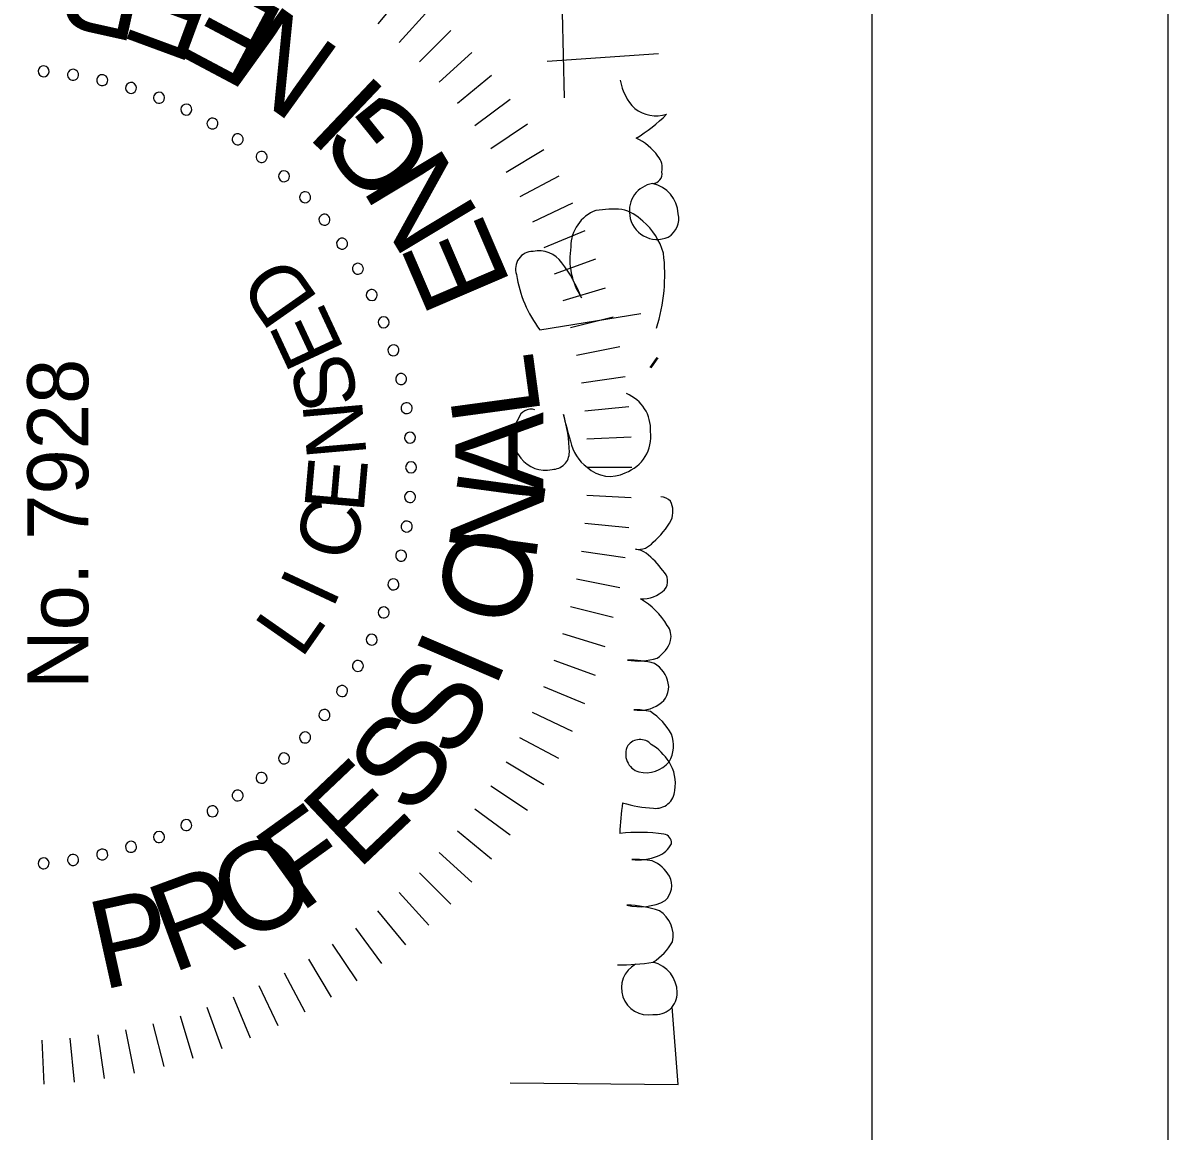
# Model space of a CAD drawing. Extents: x 916060 to 916918, y 329833 to 330383.
# Drawn here: x 916873.12 to 916910.03, y 330205.41 to 330241.13 of the extents above; entities that cross this region are included whole.
import ezdxf

# ---------------------------------------------------------------- set-up
doc = ezdxf.new("R2010")
doc.units = 0
for name, color, linetype in [('Border', 7, 'Continuous'), ('Default', 7, 'Continuous'), ('PLOT BOUNDARY', 7, 'Continuous')]:
    doc.layers.add(name, color=color, linetype=linetype)

# ---------------------------------------------------------------- blocks, each defined once
blk = doc.blocks.new('STAMP')
at = {"layer": 'Default'}
for p, q in [((-0.007955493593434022, 0.0011091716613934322), (-0.007387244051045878, 0.0011370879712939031)), ((-0.007926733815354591, 0.0007192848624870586), (-0.007360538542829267, 0.0007750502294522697)), ((-0.007878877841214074, 0.0003312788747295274), (-0.0073161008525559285, 0.00041475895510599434)), ((-0.007812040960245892, -5.391156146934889e-05), (-0.007254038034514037, 5.708212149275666e-05)), ((-0.0077263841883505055, -0.0004353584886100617), (-0.0071744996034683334, -0.00029711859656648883)), ((-0.007622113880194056, -0.0008121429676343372), (-0.007077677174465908, -0.0006469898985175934)), ((-0.00749948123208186, -0.0011833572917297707), (-0.0069638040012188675, -0.00099168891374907)), ((-0.007358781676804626, -0.0015481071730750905), (-0.006833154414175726, -0.001330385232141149)), ((-0.007200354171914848, -0.0019055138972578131), (-0.006686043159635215, -0.0016622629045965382)), ((-0.007024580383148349, -0.0022547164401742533), (-0.0065228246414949, -0.001986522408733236)), ((-0.006831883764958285, -0.002594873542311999), (-0.006343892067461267, -0.0023023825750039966)), ((-0.006622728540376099, -0.002925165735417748), (-0.0061496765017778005, -0.0026090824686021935)), ((-0.00639761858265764, -0.0032447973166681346), (-0.005940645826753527, -0.0029058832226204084)), ((-0.006157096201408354, -0.003552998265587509), (-0.005717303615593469, -0.0031920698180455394)), ((0.006157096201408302, -0.0035529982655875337), (0.005717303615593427, -0.0031920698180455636)), ((-0.005901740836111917, -0.003849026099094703), (-0.005480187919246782, -0.0034669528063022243)), ((0.005901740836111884, -0.0038490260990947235), (0.005480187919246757, -0.0034669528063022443)), ((-0.0056321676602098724, -0.0041321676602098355), (-0.00522986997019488, -0.003729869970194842)), ((0.00563216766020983, -0.0041321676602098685), (0.0052298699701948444, -0.0037298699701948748)), ((-0.005349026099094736, -0.004401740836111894), (-0.004966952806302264, -0.003980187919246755)), ((0.005349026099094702, -0.004401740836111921), (0.004966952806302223, -0.003980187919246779)), ((-0.0050529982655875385, -0.004657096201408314), (-0.004692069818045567, -0.004217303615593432)), ((0.005052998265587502, -0.004657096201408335), (0.004692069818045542, -0.004217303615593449)), ((-0.004744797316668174, -0.0048976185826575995), (-0.004405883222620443, -0.004440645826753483)), ((0.004744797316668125, -0.0048976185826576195), (0.004405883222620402, -0.0044406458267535)), ((-0.0044251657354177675, -0.005122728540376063), (-0.004109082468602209, -0.004649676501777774)), ((0.004425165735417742, -0.00512272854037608), (0.004109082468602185, -0.004649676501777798)), ((-0.004094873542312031, -0.005331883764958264), (-0.0038023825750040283, -0.004843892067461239)), ((0.0040948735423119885, -0.005331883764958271), (0.003802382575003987, -0.004843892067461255)), ((-0.0037547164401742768, -0.005524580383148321), (-0.0034865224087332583, -0.005022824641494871)), ((0.0037547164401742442, -0.005524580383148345), (0.003486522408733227, -0.005022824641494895)), ((-0.003405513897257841, -0.005700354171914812), (-0.0031622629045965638, -0.0051860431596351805)), ((0.0034055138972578, -0.005700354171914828), (0.003162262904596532, -0.005186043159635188)), ((-0.003048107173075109, -0.005858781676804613), (-0.0028303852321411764, -0.005333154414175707)), ((0.003048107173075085, -0.005858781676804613), (0.002830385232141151, -0.005333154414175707)), ((0.00523613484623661, -0.005376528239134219), (0.005338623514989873, -0.0068089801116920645)), ((-0.0026833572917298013, -0.005999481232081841), (-0.002491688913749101, -0.005463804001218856)), ((-0.0023121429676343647, -0.006122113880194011), (-0.0021469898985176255, -0.005577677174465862)), ((0.0023121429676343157, -0.006122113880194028), (0.0021469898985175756, -0.005577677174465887)), ((0.002683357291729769, -0.005999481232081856), (0.0024916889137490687, -0.005463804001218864)), ((0.004764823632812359, -0.005597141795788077), (0.005863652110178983, -0.005572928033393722)), ((-0.0019353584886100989, -0.006226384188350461), (-0.0017971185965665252, -0.005674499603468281)), ((-0.0015539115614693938, -0.006312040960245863), (-0.0014429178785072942, -0.005754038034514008)), ((0.0015539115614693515, -0.006312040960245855), (0.0014429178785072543, -0.005754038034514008)), ((0.0019353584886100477, -0.006226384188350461), (0.0017971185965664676, -0.005674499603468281)), ((-0.001168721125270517, -0.006378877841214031), (-0.0010852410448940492, -0.005816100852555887)), ((-0.0007807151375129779, -0.006426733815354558), (-0.0007249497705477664, -0.0058605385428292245)), ((-0.00039082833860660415, -0.006455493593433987), (-0.00036291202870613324, -0.005887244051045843)), ((-2.0539125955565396e-17, -0.006465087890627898), (-2.0539125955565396e-17, -0.005896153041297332)), ((0.0003908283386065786, -0.0064554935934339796), (0.0003629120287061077, -0.005887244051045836)), ((0.0007807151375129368, -0.006426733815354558), (0.0007249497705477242, -0.005860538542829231)), ((0.0011687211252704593, -0.006378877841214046), (0.0010852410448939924, -0.005816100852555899)), ((0.001282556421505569, -0.006716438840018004), (0.001411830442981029, -0.006805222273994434)), ((0.0012888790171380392, -0.0067038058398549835), (0.0014181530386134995, -0.006792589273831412))]:
    blk.add_line(p, q, dxfattribs=at)
for points in [[(-0.007938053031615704, -0.004895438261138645), (-0.007956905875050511, -0.007061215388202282), (-0.0069577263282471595, -0.006985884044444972)], [(0.0017747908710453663, -0.005281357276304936), (0.001982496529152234, -0.006583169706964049)]]:
    blk.add_lwpolyline(points, dxfattribs=at)
for centre, radius, start, end in [((-0.005106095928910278, 0.0011173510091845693), 7.111685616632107e-05, 94.28571428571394, 274.28571428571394), ((-0.005106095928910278, 0.0011173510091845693), 7.11168561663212e-05, 274.28571428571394, 94.28571428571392), ((0.005106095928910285, 0.0011173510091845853), 7.11168561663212e-05, 85.71428571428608, 265.71428571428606), ((0.005106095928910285, 0.0011173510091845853), 7.11168561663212e-05, 265.71428571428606, 85.71428571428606), ((-0.005063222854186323, 0.0007368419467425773), 7.111685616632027e-05, 98.5714285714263, 278.5714285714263), ((-0.005063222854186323, 0.0007368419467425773), 7.111685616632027e-05, 278.5714285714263, 98.5714285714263), ((0.005063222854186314, 0.0007368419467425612), 7.111685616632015e-05, 81.42857142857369, 261.4285714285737), ((0.005063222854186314, 0.0007368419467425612), 7.111685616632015e-05, 261.4285714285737, 81.42857142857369), ((-0.0049920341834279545, 0.00036060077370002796), 7.11168561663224e-05, 102.8571428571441, 282.8571428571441), ((-0.0049920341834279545, 0.00036060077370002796), 7.11168561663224e-05, 282.8571428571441, 102.85714285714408), ((0.004992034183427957, 0.00036060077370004), 7.111685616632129e-05, 77.14285714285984, 257.14285714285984), ((0.004992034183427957, 0.00036060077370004), 7.111685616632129e-05, 257.14285714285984, 77.14285714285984), ((-0.004892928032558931, -9.26841668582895e-06), 7.111685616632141e-05, 107.14285714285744, 287.14285714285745), ((-0.004892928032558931, -9.26841668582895e-06), 7.111685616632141e-05, 287.14285714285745, 107.14285714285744), ((0.004892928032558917, -9.268416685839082e-06), 7.111685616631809e-05, 72.85714285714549, 252.8571428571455), ((0.004892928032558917, -9.268416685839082e-06), 7.111685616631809e-05, 252.85714285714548, 72.85714285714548), ((-0.004766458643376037, -0.00037069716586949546), 7.111685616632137e-05, 111.42857142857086, 291.4285714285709), ((-0.004766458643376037, -0.00037069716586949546), 7.111685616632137e-05, 291.4285714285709, 111.42857142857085), ((0.0047664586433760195, -0.00037069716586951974), 7.111685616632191e-05, 68.57142857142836, 248.57142857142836), ((0.0047664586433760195, -0.00037069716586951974), 7.111685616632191e-05, 248.57142857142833, 68.57142857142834), ((-0.0046133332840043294, -0.0007216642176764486), 7.1116856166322e-05, 115.71428571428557, 295.71428571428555), ((-0.0046133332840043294, -0.0007216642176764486), 7.1116856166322e-05, 295.71428571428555, 115.71428571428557), ((0.0046133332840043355, -0.0007216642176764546), 7.111685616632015e-05, 64.28571428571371, 244.2857142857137), ((0.0046133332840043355, -0.0007216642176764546), 7.111685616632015e-05, 244.2857142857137, 64.2857142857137), ((-0.004434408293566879, -0.0010602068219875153), 7.111685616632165e-05, 119.99999999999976, 299.9999999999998), ((-0.004434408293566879, -0.0010602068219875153), 7.111685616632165e-05, 299.9999999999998, 119.99999999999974), ((0.00443440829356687, -0.0010602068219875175), 7.111685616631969e-05, 59.99999999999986, 239.99999999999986), ((0.00443440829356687, -0.0010602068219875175), 7.111685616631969e-05, 239.99999999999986, 59.99999999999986), ((-0.004230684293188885, -0.0013844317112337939), 7.111685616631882e-05, 124.28571428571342, 304.2857142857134), ((-0.004230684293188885, -0.0013844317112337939), 7.111685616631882e-05, 304.2857142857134, 124.28571428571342), ((0.004230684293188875, -0.0013844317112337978), 7.111685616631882e-05, 55.714285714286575, 235.71428571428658), ((0.004230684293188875, -0.0013844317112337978), 7.111685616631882e-05, 235.71428571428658, 55.714285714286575), ((-0.004003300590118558, -0.0016925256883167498), 7.111685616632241e-05, 308.5714285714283, 128.57142857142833), ((0.004003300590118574, -0.0016925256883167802), 7.111685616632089e-05, 51.42857142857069, 231.4285714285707), ((-0.004003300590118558, -0.0016925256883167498), 7.111685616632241e-05, 128.57142857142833, 308.5714285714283), ((0.004003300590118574, -0.0016925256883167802), 7.111685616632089e-05, 231.42857142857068, 51.42857142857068), ((-0.003753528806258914, -0.0019827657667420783), 7.11168561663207e-05, 312.85714285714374, 132.85714285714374), ((0.003753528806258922, -0.0019827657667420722), 7.111685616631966e-05, 47.14285714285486, 227.14285714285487), ((-0.003753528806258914, -0.0019827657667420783), 7.11168561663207e-05, 132.85714285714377, 312.8571428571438), ((0.003753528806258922, -0.0019827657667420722), 7.111685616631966e-05, 227.14285714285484, 47.14285714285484), ((-0.0034827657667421, -0.002253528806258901), 7.111685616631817e-05, 137.14285714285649, 317.1428571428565), ((-0.0034827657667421, -0.002253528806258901), 7.111685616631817e-05, 317.1428571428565, 137.14285714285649), ((0.0034827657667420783, -0.0022535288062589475), 7.111685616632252e-05, 42.857142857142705, 222.85714285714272), ((0.0034827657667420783, -0.0022535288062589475), 7.111685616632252e-05, 222.8571428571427, 42.85714285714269), ((-0.0031925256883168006, -0.0025033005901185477), 7.111685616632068e-05, 141.42857142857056, 321.42857142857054), ((-0.0031925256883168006, -0.0025033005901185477), 7.111685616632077e-05, 321.42857142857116, 141.4285714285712), ((0.0031925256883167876, -0.002503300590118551), 7.111685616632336e-05, 38.57142857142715, 218.57142857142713), ((0.0031925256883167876, -0.002503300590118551), 7.111685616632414e-05, 218.57142857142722, 38.57142857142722), ((-0.0028844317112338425, -0.0027306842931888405), 7.111685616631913e-05, 145.7142857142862, 325.71428571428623), ((-0.0028844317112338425, -0.0027306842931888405), 7.111685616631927e-05, 325.7142857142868, 145.71428571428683), ((0.002884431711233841, -0.0027306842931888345), 7.111685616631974e-05, 34.28571428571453, 214.28571428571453), ((0.002884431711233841, -0.0027306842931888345), 7.111685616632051e-05, 214.28571428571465, 34.28571428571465), ((-0.0025602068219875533, -0.0029344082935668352), 7.111685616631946e-05, 149.99999999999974, 329.9999999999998), ((-0.0025602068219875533, -0.0029344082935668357), 7.111685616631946e-05, 329.9999999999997, 149.99999999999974), ((0.0025602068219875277, -0.0029344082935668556), 7.111685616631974e-05, 30.000000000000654, 210.00000000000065), ((0.0025602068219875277, -0.002934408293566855), 7.111685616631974e-05, 210.00000000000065, 30.000000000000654), ((-0.0022216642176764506, -0.0031133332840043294), 7.111685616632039e-05, 154.2857142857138, 334.28571428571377), ((-0.0022216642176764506, -0.0031133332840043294), 7.111685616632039e-05, 334.2857142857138, 154.2857142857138), ((0.0022216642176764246, -0.0031133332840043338), 7.111685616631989e-05, 25.714285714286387, 205.71428571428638), ((0.0022216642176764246, -0.0031133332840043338), 7.111685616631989e-05, 205.71428571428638, 25.714285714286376), ((-0.0018706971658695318, -0.003266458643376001), 7.111685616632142e-05, 158.57142857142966, 338.5714285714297), ((-0.0018706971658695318, -0.0032664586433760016), 7.111685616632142e-05, 338.57142857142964, 158.57142857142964), ((0.0018706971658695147, -0.0032664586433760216), 7.111685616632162e-05, 21.428571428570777, 201.42857142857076), ((0.0018706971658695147, -0.0032664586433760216), 7.111685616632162e-05, 201.42857142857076, 21.428571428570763), ((-0.0015092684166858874, -0.003392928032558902), 7.111685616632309e-05, 162.85714285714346, 342.85714285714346), ((-0.0015092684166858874, -0.003392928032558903), 7.111685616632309e-05, 342.85714285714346, 162.85714285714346), ((0.0015092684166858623, -0.0033929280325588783), 7.111685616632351e-05, 17.142857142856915, 197.1428571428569), ((0.0015092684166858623, -0.0033929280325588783), 7.111685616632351e-05, 197.1428571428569, 17.14285714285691), ((-0.0011393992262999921, -0.0034920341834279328), 7.111685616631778e-05, 167.14285714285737, 347.14285714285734), ((-0.0011393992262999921, -0.0034920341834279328), 7.111685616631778e-05, 347.14285714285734, 167.14285714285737), ((-0.0007631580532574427, -0.003563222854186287), 7.111685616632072e-05, 351.4285714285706, 171.4285714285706), ((-0.0003826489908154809, -0.003606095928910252), 7.111685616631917e-05, 355.7142857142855, 175.7142857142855), ((0.0003826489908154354, -0.0036060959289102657), 7.111685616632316e-05, 4.285714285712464, 184.28571428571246), ((0.0007631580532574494, -0.0035632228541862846), 7.111685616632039e-05, 8.571428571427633, 188.57142857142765), ((0.0011393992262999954, -0.0034920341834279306), 7.111685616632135e-05, 12.857142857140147, 192.85714285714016), ((0.0011393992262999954, -0.0034920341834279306), 7.111685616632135e-05, 192.85714285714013, 12.857142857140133), ((-0.0007631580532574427, -0.003563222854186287), 7.111685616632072e-05, 171.4285714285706, 351.4285714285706), ((-0.0003826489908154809, -0.003606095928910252), 7.111685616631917e-05, 175.71428571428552, 355.71428571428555), ((-1.2628786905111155e-17, -0.0036204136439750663), 7.111685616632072e-05, 0, 180), ((-1.2628786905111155e-17, -0.0036204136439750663), 7.111685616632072e-05, 180, 0), ((0.0003826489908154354, -0.0036060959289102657), 7.111685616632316e-05, 184.28571428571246, 4.285714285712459), ((0.0007631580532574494, -0.0035632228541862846), 7.111685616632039e-05, 188.57142857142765, 8.571428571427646), ((0.00039604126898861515, -0.005375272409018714), 0.00043958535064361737, 57.64755033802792, 128.97245422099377), ((0.0005805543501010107, -0.005165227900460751), 0.00016909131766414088, 342.3611945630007, 72.54487353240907), ((0.0027009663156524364, -0.006477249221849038), 0.001512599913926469, 98.17812986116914, 127.75649827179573), ((0.0025607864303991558, -0.005191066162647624), 0.0002239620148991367, 359.61429023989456, 109.56218572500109), ((0.00036114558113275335, -0.0053488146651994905), 0.0003972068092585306, 127.45926190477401, 192.9614203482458), ((0.0024288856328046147, -0.00526578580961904), 0.0003633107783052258, 304.8740098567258, 11.625468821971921), ((0.00019608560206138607, -0.005439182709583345), 0.0002220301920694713, 179.67057284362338, 269.694601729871), ((0.00015503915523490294, -0.003868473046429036), 0.001793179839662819, 271.2738092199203, 287.01217780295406), ((0.002166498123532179, -0.011827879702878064), 0.006419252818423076, 103.3923944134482, 106.55297850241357), ((0.0015502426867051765, -0.00415818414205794), 0.0017765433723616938, 290.99837671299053, 307.69878588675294), ((0.0004564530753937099, -0.0062299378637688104), 0.0005678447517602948, 102.0773813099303, 143.39383108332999), ((0.0026896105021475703, -0.006582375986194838), 0.0009159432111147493, 80.29637939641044, 123.29138431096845), ((0.0028457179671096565, -0.006179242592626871), 0.0004997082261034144, 20.58705533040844, 90.19763829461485), ((0.00031613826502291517, -0.006186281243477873), 0.0004319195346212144, 136.9297266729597, 206.7934360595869), ((0.0014539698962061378, -0.006245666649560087), 0.0018752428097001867, 357.2040173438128, 7.418903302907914), ((-0.00671307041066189, -0.006678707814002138), 0.0003465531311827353, 28.430349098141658, 189.68707560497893), ((-0.003955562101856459, -0.006312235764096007), 0.002461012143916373, 179.30402472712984, 190.0665804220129), ((-0.007015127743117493, -0.0065631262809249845), 0.0023079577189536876, 352.1195763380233, 6.249520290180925), ((-0.004786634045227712, -0.009314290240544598), 0.003003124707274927, 81.15725195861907, 88.74550427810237), ((-0.002857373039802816, -0.006810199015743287), 0.001539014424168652, 162.47862001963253, 177.5735090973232), ((0.0027994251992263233, -0.006216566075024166), 0.0005411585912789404, 313.71200852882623, 347.12598992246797), ((0.005109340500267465, -0.0069995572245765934), 0.000693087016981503, 99.83623703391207, 134.2279465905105), ((-0.007040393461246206, -0.006369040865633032), 0.0013973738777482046, 341.03759348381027, 358.5906169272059), ((-0.004987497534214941, -0.006577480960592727), 0.0006786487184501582, 165.1377733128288, 207.96825790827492), ((-0.006329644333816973, -0.006519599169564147), 0.0012732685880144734, 350.5388137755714, 2.446920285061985), ((-0.004310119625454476, -0.006538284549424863), 0.0007509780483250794, 174.41813129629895, 200.30191948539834), ((-0.0037000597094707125, -0.006623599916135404), 0.00023723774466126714, 61.91684207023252, 163.66717131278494), ((-0.0037052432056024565, -0.0065716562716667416), 0.0001960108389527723, 312.7382758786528, 53.40100716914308), ((-0.003974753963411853, -0.006503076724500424), 0.0008496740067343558, 346.26214121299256, 0.7257075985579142), ((-0.002682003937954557, -0.006568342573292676), 0.00044961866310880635, 170.2648919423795, 213.2954708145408), ((-0.00388024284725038, -0.006412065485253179), 0.0013948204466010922, 345.72048696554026, 0.12433676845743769), ((-0.0016914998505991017, -0.006545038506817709), 0.0008054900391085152, 170.27954956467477, 197.78532003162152), ((0.0003962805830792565, -0.006217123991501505), 0.0004936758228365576, 199.38474076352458, 277.55079490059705), ((0.0004891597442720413, -0.006207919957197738), 0.0004993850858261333, 266.784921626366, 337.7362429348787), ((0.0032953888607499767, -0.006791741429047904), 0.00035634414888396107, 97.37079091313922, 203.8922211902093), ((0.0033059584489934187, -0.006794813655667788), 0.0003608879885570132, 9.655140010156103, 98.97262191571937), ((-0.0035430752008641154, -0.006644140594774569), 0.0003944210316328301, 167.2189950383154, 230.16055614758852), ((-0.002536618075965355, -0.006083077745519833), 0.0009765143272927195, 300.6803608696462, 329.51258202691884), ((-0.0012666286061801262, -0.006594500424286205), 0.00042878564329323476, 177.86300386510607, 223.17874837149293), ((-0.0013865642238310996, -0.006474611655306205), 0.0003320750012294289, 327.8843366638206, 353.1980671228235), ((-0.0008025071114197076, -0.006544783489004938), 0.0002561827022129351, 173.08541670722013, 230.55848375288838), ((0.002532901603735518, -0.0060711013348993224), 0.0008355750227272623, 286.05704557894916, 320.0421489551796), ((0.003588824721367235, -0.00621969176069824), 0.0007209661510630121, 306.1913846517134, 335.23134174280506), ((0.005998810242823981, -0.005456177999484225), 0.0020534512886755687, 211.2594929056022, 225.2513717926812), ((0.004994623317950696, -0.006780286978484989), 0.0004614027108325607, 143.047197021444, 196.91634387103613), ((-0.006777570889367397, -0.006772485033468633), 0.00027937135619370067, 172.70712454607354, 271.16395527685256), ((-0.006783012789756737, -0.006633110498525), 0.0004188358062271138, 271.5209447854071, 344.87406906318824), ((-0.005754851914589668, -0.006345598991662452), 0.0007393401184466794, 212.4592088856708, 240.63114206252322), ((-0.0055308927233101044, -0.006522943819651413), 0.0005014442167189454, 301.1133493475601, 335.74975916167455), ((-0.004152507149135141, -0.006775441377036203), 0.00024439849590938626, 172.85451562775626, 266.8151593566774), ((-0.00421927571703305, -0.006314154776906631), 0.0007614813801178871, 303.79189499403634, 328.18256979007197), ((-0.0038004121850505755, -0.006299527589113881), 0.000766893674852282, 298.0105046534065, 328.09350966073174), ((-0.00285343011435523, -0.006566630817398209), 0.0003761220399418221, 280.5798823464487, 329.7517392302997), ((-0.0020051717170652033, -0.0059200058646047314), 0.0011594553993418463, 305.5205731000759, 320.90595982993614), ((-0.0001785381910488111, -0.0060637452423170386), 0.0010391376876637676, 220.79179678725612, 241.16030041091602), ((0.0024869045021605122, -0.0045618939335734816), 0.0023287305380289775, 252.701645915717, 276.8342307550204), ((0.0032445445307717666, -0.006637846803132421), 0.00042819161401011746, 273.5716384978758, 346.98387133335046), ((0.0037841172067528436, -0.006733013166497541), 0.00012238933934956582, 180.59606692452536, 282.14231124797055), ((-0.006036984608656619, -0.006622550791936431), 0.0003760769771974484, 257.6460165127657, 327.7710077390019), ((-0.005391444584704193, -0.006712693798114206), 0.0002677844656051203, 223.12676578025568, 296.5429712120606), ((-0.004715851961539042, -0.006689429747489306), 0.00031800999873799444, 200.1253724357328, 244.48124886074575), ((-0.004842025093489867, -0.006862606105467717), 0.00011432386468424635, 264.56536252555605, 351.47104640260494), ((-0.0028340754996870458, -0.006679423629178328), 0.00026169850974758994, 211.24435430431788, 280.94854976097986), ((-0.0021179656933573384, -0.00658432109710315), 0.00039838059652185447, 211.26450698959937, 253.32703764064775), ((-0.0021804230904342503, -0.006741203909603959), 0.00023065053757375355, 257.01114107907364, 308.02112433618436), ((-0.0014677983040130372, -0.006749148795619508), 0.0001780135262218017, 231.21384232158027, 319.94914487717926), ((-0.0005623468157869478, -0.006834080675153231), 0.00018159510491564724, 314.66347430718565, 358.2957841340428), ((0.003211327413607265, -0.006788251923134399), 0.0002833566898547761, 211.44349084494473, 282.2024112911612), ((0.0038601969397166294, -0.006618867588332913), 0.000239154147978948, 257.8497316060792, 310.1947013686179), ((-0.00407546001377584, -0.006500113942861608), 0.0005271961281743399, 260.1016649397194, 302.042575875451), ((-0.0035868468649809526, -0.00658750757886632), 0.00041578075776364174, 239.8376850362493, 290.64484911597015), ((-0.0005688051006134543, -0.006705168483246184), 0.00029083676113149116, 247.5695171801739, 297.4590386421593)]:
    blk.add_arc(centre, radius, start, end, dxfattribs=at)
for s, height, p in [('No. 7928', 0.0007851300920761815, (-0.002860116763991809, 0.0005420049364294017)), ('A', 0.0011378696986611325, (-0.0003007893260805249, -0.005327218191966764))]:
    blk.add_text(s, height=height, dxfattribs=at).set_placement(p)
for s, height, rotation, p in [('R', 0.001137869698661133, 77.5, (0.006589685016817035, -0.0003191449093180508)), ('P', 0.0011378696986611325, 282.5, (-0.006741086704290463, 0.00036378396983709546)), ('E', 0.0011378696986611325, 69.75, (0.006276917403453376, -0.001210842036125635)), ('R', 0.0011378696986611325, 290.25, (-0.00652629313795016, -0.0005348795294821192)), ('E', 0.0011378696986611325, 62, (0.005854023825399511, -0.002032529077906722)), ('O', 0.0011378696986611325, 298, (-0.006169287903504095, -0.0014396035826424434)), ('N', 0.001137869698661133, 54.25000000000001, (0.005352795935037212, -0.0027499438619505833)), ('D', 0.0007680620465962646, 34.99999999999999, (0.002169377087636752, -0.0024365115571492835)), ('F', 0.001137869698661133, 305.75, (-0.0057573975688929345, -0.002187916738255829)), ('L', 0.0007680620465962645, 324.99999999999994, (-0.002479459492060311, -0.00220631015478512)), ('E', 0.0007680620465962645, 25.000000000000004, (0.001513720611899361, -0.002766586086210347)), ('I', 0.0007680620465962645, 335, (-0.001841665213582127, -0.002604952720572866)), ('C', 0.0007680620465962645, 345, (-0.0012469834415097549, -0.0028524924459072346)), ('S', 0.0007680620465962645, 14.999999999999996, (0.0008506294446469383, -0.0029637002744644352)), ('E', 0.0011378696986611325, 313.5, (-0.005207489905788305, -0.0029306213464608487)), ('E', 0.0007680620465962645, 355, (-0.0005969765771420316, -0.00300722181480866)), ('N', 0.0007680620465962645, 5, (0.0001499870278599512, -0.003047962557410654)), ('I', 0.001137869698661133, 46.499999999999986, (0.004817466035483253, -0.003341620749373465)), ('G', 0.001137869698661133, 38.75000000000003, (0.004038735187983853, -0.004012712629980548)), ('S', 0.0011378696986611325, 321.25, (-0.004535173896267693, -0.0036142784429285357)), ('N', 0.0011378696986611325, 30.999999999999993, (0.0032404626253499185, -0.004517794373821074)), ('S', 0.0011378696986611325, 328.99999999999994, (-0.003804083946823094, -0.004179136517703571)), ('E', 0.0011378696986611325, 23.249999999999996, (0.0023543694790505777, -0.004919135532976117)), ('I', 0.0011378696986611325, 336.75, (-0.0028749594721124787, -0.00469547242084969)), ('O', 0.001137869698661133, 344.5, (-0.0021143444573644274, -0.004998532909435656)), ('N', 0.001137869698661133, 352.25, (-0.001239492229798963, -0.005221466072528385)), ('L', 0.001137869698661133, 7.75, (0.0006711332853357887, -0.0052988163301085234))]:
    blk.add_text(s, height=height, rotation=rotation, dxfattribs=at).set_placement(p)

msp = doc.modelspace()

# ---------------------------------------------------------------- linework, layer by layer
at = {"layer": 'Border'}
msp.add_line((916900.4925019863, 329848.18464868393), (916900.4925019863, 330373.1835986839), dxfattribs=at)
at = {"layer": 'PLOT BOUNDARY'}
msp.add_lwpolyline([(916060.027451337, 329832.8741154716), (916910.0257513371, 329832.8741154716), (916910.0257513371, 330382.8730154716), (916060.027451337, 330382.8730154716)], close=True, dxfattribs=at)

# ---------------------------------------------------------------- block references
at = {"layer": 'Border', "xscale": 2499.999999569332, "yscale": 2499.999999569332, "rotation": 90}
msp.add_blockref('STAMP', (916876.5782560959, 330226.80272714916), dxfattribs=at)

doc.saveas('drawing.dxf')
